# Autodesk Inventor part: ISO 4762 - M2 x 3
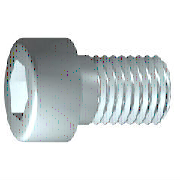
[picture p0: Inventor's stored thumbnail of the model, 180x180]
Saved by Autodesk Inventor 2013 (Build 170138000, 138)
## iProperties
Created: 2012-02
Part Number: ISO 4762 - M2 x 3
Material: Edelstahl, 440C
Description: Innensechskantschraube
Document SubType Name: Modeling
Standard: ISO 4762
Designer: rYan
Standard Revision: 1998
Standards Organization: DIN
Language: de-DE
Size Designation: M2 x 3
Categories: <MemberInstance><Categories><Category DisplayName="Verbindungselemente" InternalName="e4da775c-781d-43d5-af7c-5136215cf5a6" Mnemonic="FSTN"><Category DisplayNam
Density: 7.75 g/cm^3
IsCustomPart: 0
Author: rYan
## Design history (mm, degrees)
sketch "Skizze1"
  geometry: L1 (-0.5, 0)-(3, 0); L2 (3, 0)-(3, 1); L3 (3, 1)-(1, 1); L4 (1, 1)-(0.755, 1); L5 (0.755, 1)-(0, 1); L6 (0, 1)-(0, 1.9); L7 (0, 1.9)-(-2, 1.9); L8 (-2, 1.9)-(-2, 0.866); L9 (-2, 0.866)-(-1, 0.866); L10 (-1, 0.866)-(-0.5, 0); L11 (-3, 0)-(4, 0) reference; L12 (0, -0.38)-(0, 2.28) reference; L13 (1, 1)-(0, 1)
  constraints: 22 end point, 6 parallel, 2 collinear, 2 perpendicular, 1 horizontal, 1 point on line
  dimensions: "d1" = 2 distance from line of L3.end L2 (= GEL); "d2" = 0.24548 distance of L4.end L3.end (computed from GAL); "d3" = 2 distance between parallel lines of L8 L6 (= KOH); "d4" = 1 distance of L8.end L9.end (= INTI); "d5" = 60 deg angle of L10 L1; "d6" = 2 diameter of L3 L1 (= GD); "d7" = 2 diameter of L5 L1 (= BDM); "d8" = 1.73205 diameter of L9 L1 (= 1.1547 x SW); "d9" = 3.8 diameter of L7 L1 (= KOD); "d26" = 3 distance between parallel lines of L12 L2 (= NLG)
revolve "Körper" sketch "Skizze1" stored, may be unused: angle "d10" = 90 deg
sketch "Skizze2"
  geometry: L1 (0, -2.66)-(0, 2.66) reference; L2 (-2.66, 0)-(2.66, 0) reference; L3 (0.866, 0)-(0.433, -0.75); L4 (0.433, -0.75)-(-0.433, -0.75); L5 (-0.433, -0.75)-(-0.866, 0); L6 (-0.866, 0)-(-0.433, 0.75); L7 (-0.433, 0.75)-(0.433, 0.75); L8 (0.433, 0.75)-(0.866, 0); 2 further points
  constraints: 12 end point, 1 coincident, 1 horizontal alignment, 1 point on line, 12 other
extrude "Loch" join sketch "Skizze2" stored distance "d11" = 10; taper "d12" = 0 deg
workplane "Work Plane1"
fillet "Fillet2" dims "d30" = 0.1 (= R)
body "Solid1"
fillet "Rundung1" dims "d17" = 0.2 (= RR)
feature "Gewinde" dims "d13" = 2 (= GEL), "d14" = 0
chamfer "Fase1" distance "d15" = 0.24538 (= -0.5 x SPD + 0.5 x GD); stored, may be unused: second distance "d16" = 0.24538 (= GUL), angle "d27" = 45 deg
other parameters: "GD" = 2 [user parameter; used in 2 equation terms], "NLG" = 3 [user parameter; used in 1 equation term], "GEL" = 2 [user parameter; used in 2 equation terms], "KOD" = 3.8 [user parameter; used in 1 equation term], "KOH" = 2 [user parameter; used in 1 equation term], "INTI" = 1 [user parameter; used in 1 equation term], "GAL" = 0.24538 (= 0.61345 x PTC) [user parameter; used in 1 equation term], "GUL" = 0.24538 (= 0.61345 x PTC) [user parameter; used in 1 equation term], "BDM" = 2 (= NND) [user parameter; used in 1 equation term], "SW" = 1.5 [user parameter; used in 2 equation terms], "RR" = 0.2 [user parameter; used in 1 equation term], "SPD" = 1.50924 (= NND - 1.2269 x PTC) [user parameter; used in 1 equation term], "d19" = 0, "d28" = 0, "d29" = 0, "R" = 0.1 [user parameter; used in 1 equation term], "TOA" = 30 deg [user parameter], "GD1" = 1.50924 (= THREADDIA - 1.2269 x PTC) [user parameter], "THREADDIA" = 2 [user parameter; used in 1 equation term], "FAWI" = 45 deg [user parameter], "TPU" = 25 (computed from PTC) [user parameter], "PTC" = 0.4 [user parameter; used in 5 equation terms], "NND" = 2 [user parameter; used in 2 equation terms], "E0" = 1.7325 (= 1.155 x SW) [user parameter]
